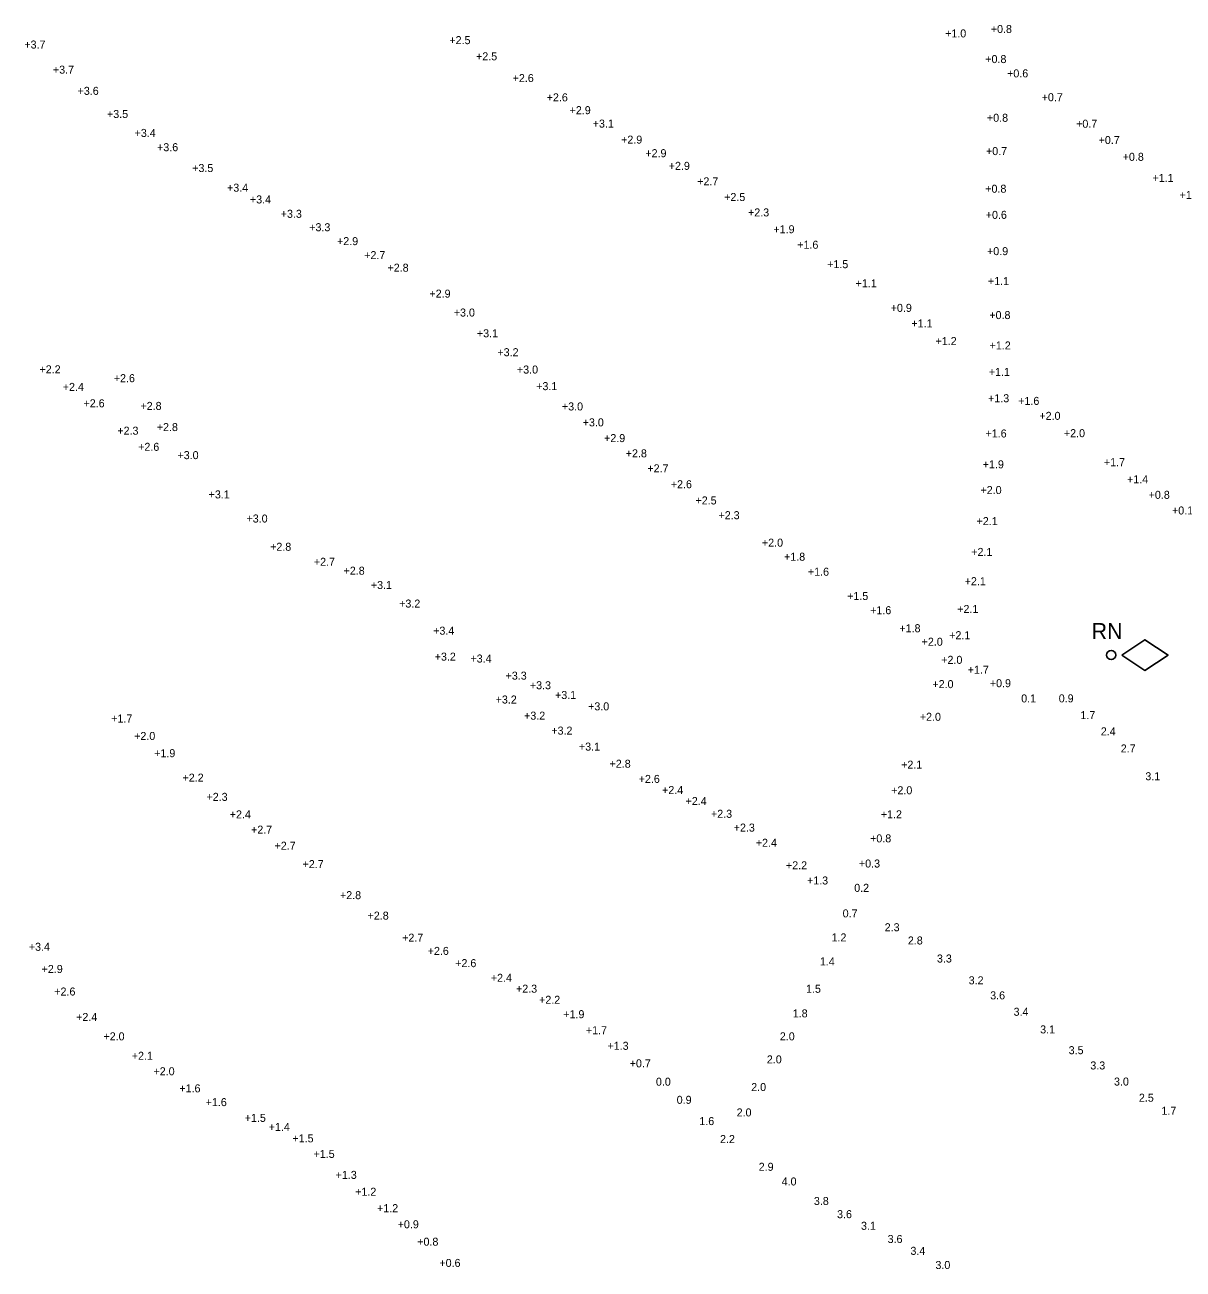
# Model space of a CAD drawing. Extents: x 837127 to 848654, y 3074248 to 3079868.
# Drawn here: x 842462.9 to 842915.3, y 3078028.5 to 3078514.3 of the extents above; entities that cross this region are included whole.
import ezdxf

# ---------------------------------------------------------------- set-up
doc = ezdxf.new("R2010")
doc.units = 0
doc.layers.add('V-CHAN-NAID', color=7, linetype='Continuous')
doc.layers.add('V-HYDS-SOUN', color=7, linetype='Continuous')

msp = doc.modelspace()

# ---------------------------------------------------------------- linework, layer by layer
at = {"layer": 'V-CHAN-NAID'}
msp.add_lwpolyline([(842891.41, 3078268.27), (842900.41, 3078262.27), (842909.41, 3078268.27), (842900.41, 3078274.27)], close=True, dxfattribs=at)
msp.add_circle((842887.21, 3078268.27), 1.8, dxfattribs=at)

# ---------------------------------------------------------------- texts
msp.add_text('RN', height=6.25, dxfattribs=at).set_placement((842879.57, 3078274.51))
at = {"layer": 'V-HYDS-SOUN'}
for s, p in [('+0.8 ', (842840.19, 3078511.13)), ('+3.7 ', (842462.69, 3078505.06)), ('+2.5 ', (842628.7, 3078506.78)), ('+1.0 ', (842822.34, 3078509.41)), ('+2.5 ', (842639.11, 3078500.47)), ('+3.7 ', (842473.86, 3078495.26)), ('+0.8 ', (842838.03, 3078499.39)), ('+2.6 ', (842653.42, 3078491.98)), ('+0.6 ', (842846.55, 3078493.81)), ('+3.6 ', (842483.49, 3078486.98)), ('+2.6 ', (842666.71, 3078484.44)), ('+0.7 ', (842860.05, 3078484.5)), ('+3.5 ', (842494.97, 3078477.95)), ('+2.9 ', (842675.67, 3078479.44)), ('+0.8 ', (842838.68, 3078476.47)), ('+3.1 ', (842684.69, 3078474.2)), ('+0.7 ', (842873.51, 3078474.15)), ('+3.4 ', (842505.76, 3078470.55)), ('+2.9 ', (842695.78, 3078467.94)), ('+0.7 ', (842882.31, 3078467.78)), ('+3.6 ', (842514.53, 3078464.98)), ('+2.9 ', (842705.25, 3078462.64)), ('+0.7 ', (842838.31, 3078463.47)), ('+0.8 ', (842891.7, 3078461.23)), ('+3.5 ', (842528.25, 3078456.85)), ('+2.9 ', (842714.39, 3078457.7)), ('+2.7 ', (842725.5, 3078451.65)), ('+1.1 ', (842903.34, 3078453.01)), ('+3.4 ', (842541.86, 3078449.18)), ('+0.8 ', (842838.02, 3078448.77)), ('+3.4 ', (842550.81, 3078444.59)), ('+2.5 ', (842736.04, 3078445.53)), ('+1.3 ', (842913.92, 3078446.34)), ('+3.3 ', (842562.84, 3078438.98)), ('+2.3 ', (842745.36, 3078439.52)), ('+0.6 ', (842838.21, 3078438.57)), ('+3.3 ', (842573.97, 3078433.74)), ('+1.9 ', (842755.27, 3078432.95)), ('+2.9 ', (842584.82, 3078428.31)), ('+2.7 ', (842595.43, 3078422.85)), ('+1.6 ', (842764.58, 3078426.9)), ('+0.9 ', (842838.71, 3078424.4)), ('+2.8 ', (842604.54, 3078417.94)), ('+1.5 ', (842776.27, 3078419.32)), ('+1.1 ', (842839.07, 3078412.73)), ('+2.9 ', (842620.92, 3078407.81)), ('+1.1 ', (842787.39, 3078411.82)), ('+3.0 ', (842630.43, 3078400.43)), ('+0.9 ', (842801.09, 3078402.25)), ('+0.8 ', (842839.61, 3078399.44)), ('+1.1 ', (842809.18, 3078396.19)), ('+3.1 ', (842639.46, 3078392.33)), ('+1.2 ', (842818.59, 3078389.29)), ('+3.2 ', (842647.48, 3078384.94)), ('+1.2 ', (842839.71, 3078387.57)), ('+2.2 ', (842468.6, 3078378.25)), ('+2.6 ', (842497.63, 3078374.8)), ('+3.0 ', (842655.1, 3078378.17)), ('+1.1 ', (842839.4, 3078377.27)), ('+2.4 ', (842477.7, 3078371.4)), ('+3.1 ', (842662.61, 3078371.69)), ('+2.6 ', (842485.8, 3078365)), ('+2.8 ', (842508.04, 3078363.98)), ('+1.3 ', (842839.12, 3078366.97)), ('+1.6 ', (842850.89, 3078365.94)), ('+3.0 ', (842672.67, 3078363.77)), ('+2.0 ', (842859.16, 3078360.1)), ('+2.3 ', (842499.01, 3078354.3)), ('+2.8 ', (842514.42, 3078355.71)), ('+3.0 ', (842680.78, 3078357.56)), ('+2.9 ', (842689.13, 3078351.41)), ('+1.6 ', (842838.12, 3078353.22)), ('+2.0 ', (842868.74, 3078353.33)), ('+2.6 ', (842507.14, 3078348)), ('+3.0 ', (842522.5, 3078344.76)), ('+2.8 ', (842697.6, 3078345.45)), ('+1.9 ', (842837.04, 3078341.16)), ('+1.7 ', (842884.36, 3078342.01)), ('+2.7 ', (842706.04, 3078339.6)), ('+1.4 ', (842893.4, 3078335.34)), ('+2.6 ', (842715.2, 3078333.39)), ('+2.0 ', (842836.16, 3078331.13)), ('+3.1 ', (842534.67, 3078329.42)), ('+2.5 ', (842724.84, 3078327.07)), ('+0.8 ', (842901.84, 3078329.26)), ('+2.3 ', (842733.82, 3078321.31)), ('+0.1 ', (842910.96, 3078323.15)), ('+3.0 ', (842549.46, 3078320.01)), ('+2.1 ', (842834.63, 3078319.01)), ('+2.0 ', (842750.79, 3078310.58)), ('+2.8 ', (842558.69, 3078308.98)), ('+2.1 ', (842832.56, 3078306.96)), ('+2.7 ', (842575.77, 3078303.11)), ('+1.8 ', (842759.43, 3078305.09)), ('+2.8 ', (842587.37, 3078299.64)), ('+1.6 ', (842768.75, 3078299.23)), ('+3.1 ', (842598.03, 3078294.05)), ('+2.1 ', (842829.98, 3078295.54)), ('+3.2 ', (842609.09, 3078286.81)), ('+1.5 ', (842784.07, 3078289.76)), ('+1.6 ', (842793.06, 3078284.21)), ('+2.1 ', (842827.08, 3078284.7)), ('+1.8 ', (842804.49, 3078277.18)), ('+3.4 ', (842622.37, 3078276.22)), ('+2.0 ', (842813.17, 3078271.9)), ('+2.1 ', (842823.93, 3078274.45)), ('+3.2 ', (842622.97, 3078266.09)), ('+3.4 ', (842636.94, 3078265.34)), ('+2.0 ', (842820.83, 3078264.83)), ('+3.3 ', (842650.66, 3078258.67)), ('+1.7 ', (842831.18, 3078260.98)), ('+3.3 ', (842660.15, 3078254.92)), ('+2.0 ', (842817.37, 3078255.35)), ('+0.9 ', (842839.81, 3078255.71)), ('+3.2 ', (842646.78, 3078249.34)), ('+3.1 ', (842669.97, 3078251.11)), ('0.1', (842852.06, 3078249.77)), ('0.9', (842866.72, 3078249.79)), ('+3.2 ', (842657.88, 3078243.04)), ('+3.0 ', (842682.89, 3078246.67)), ('+2.0 ', (842812.46, 3078242.59)), ('1.7', (842875.18, 3078243.24)), ('+1.7 ', (842496.62, 3078241.93)), ('+2.0 ', (842505.58, 3078235.11)), ('+3.2 ', (842668.53, 3078237.2)), ('2.4', (842883.15, 3078236.9)), ('+1.9 ', (842513.4, 3078228.39)), ('+3.1 ', (842679.31, 3078230.96)), ('2.7', (842890.93, 3078230.23)), ('+2.8 ', (842691.28, 3078224.27)), ('+2.1 ', (842805.16, 3078223.91)), ('+2.2 ', (842524.47, 3078218.84)), ('+2.6 ', (842702.65, 3078218.34)), ('3.1', (842900.55, 3078219.38)), ('+2.4 ', (842711.78, 3078214)), ('+2.0 ', (842801.27, 3078213.91)), ('+2.3 ', (842533.84, 3078211.34)), ('+2.4 ', (842720.96, 3078209.71)), ('+2.4 ', (842542.92, 3078204.49)), ('+2.3 ', (842730.89, 3078204.72)), ('+1.2 ', (842797.22, 3078204.52)), ('+2.3 ', (842739.77, 3078199.34)), ('+2.7 ', (842551.24, 3078198.53)), ('+0.8 ', (842793.04, 3078195.13)), ('+2.7 ', (842560.42, 3078192.26)), ('+2.4 ', (842748.39, 3078193.41)), ('+2.7 ', (842571.36, 3078185.08)), ('+2.2 ', (842760.18, 3078184.61)), ('+0.3 ', (842788.68, 3078185.31)), ('+1.3 ', (842768.39, 3078178.69)), ('0.2', (842786.84, 3078175.81)), ('+2.8 ', (842585.98, 3078172.96)), ('+2.8 ', (842596.76, 3078164.97)), ('0.7', (842782.33, 3078165.85)), ('2.3', (842798.74, 3078160.43)), ('+2.7 ', (842610.25, 3078156.36)), ('1.2', (842777.98, 3078156.45)), ('2.8', (842807.79, 3078155.26)), ('+3.4 ', (842464.43, 3078152.8)), ('+2.6 ', (842620.24, 3078151.19)), ('+2.6 ', (842630.98, 3078146.42)), ('1.4', (842773.42, 3078147.07)), ('3.3', (842819.15, 3078148.22)), ('+2.9 ', (842469.44, 3078144.14)), ('+2.4 ', (842644.89, 3078140.68)), ('+2.3 ', (842654.73, 3078136.44)), ('1.5', (842768.02, 3078136.41)), ('3.2', (842831.53, 3078139.71)), ('+2.6 ', (842474.39, 3078135.33)), ('+2.2 ', (842663.74, 3078132.1)), ('3.6', (842839.95, 3078133.83)), ('+1.9 ', (842673.2, 3078126.49)), ('1.8', (842762.83, 3078126.8)), ('3.4', (842849.08, 3078127.43)), ('+2.4 ', (842482.91, 3078125.38)), ('+2.0 ', (842493.59, 3078117.83)), ('+1.7 ', (842682.03, 3078120.23)), ('2.0', (842757.78, 3078117.83)), ('3.1', (842859.46, 3078120.54)), ('+1.3 ', (842690.46, 3078114.14)), ('3.5', (842870.6, 3078112.43)), ('+2.1 ', (842504.65, 3078110.23)), ('+0.7 ', (842699.14, 3078107.3)), ('2.0', (842752.71, 3078108.83)), ('+2.0 ', (842513.14, 3078104.2)), ('3.3', (842879.06, 3078106.47)), ('+1.6 ', (842523.24, 3078097.53)), (' 0.0', (842708.22, 3078100.12)), ('2.0', (842746.6, 3078098.04)), ('3.0', (842888.31, 3078100.18)), ('+1.6 ', (842533.51, 3078092.15)), ('0.9', (842717.5, 3078093.06)), ('2.5', (842898.03, 3078093.87)), ('2.0', (842740.91, 3078088.13)), ('1.7', (842906.83, 3078088.78)), ('+1.5 ', (842548.77, 3078086.01)), ('+1.4 ', (842558.14, 3078082.46)), ('1.6', (842726.34, 3078084.75)), ('+1.5 ', (842567.41, 3078078.01)), ('2.2', (842734.42, 3078077.74)), ('+1.5 ', (842575.65, 3078071.94)), ('+1.3 ', (842584.28, 3078063.74)), ('2.9', (842749.53, 3078066.91)), ('4.0', (842758.5, 3078061.18)), ('+1.2 ', (842591.91, 3078057.17)), ('3.8', (842771.09, 3078053.56)), ('+1.2 ', (842600.47, 3078050.75)), ('3.6', (842780.14, 3078048.4)), ('+0.9 ', (842608.52, 3078044.46)), ('3.1', (842789.49, 3078043.87)), ('3.6', (842799.88, 3078038.72)), ('+0.8 ', (842616.16, 3078037.65)), ('3.4', (842808.79, 3078034.09)), ('+0.6 ', (842624.81, 3078029.37)), ('3.0', (842818.56, 3078028.56))]:
    msp.add_text(s, height=3.125, dxfattribs=at).set_placement(p)

doc.saveas('drawing.dxf')
